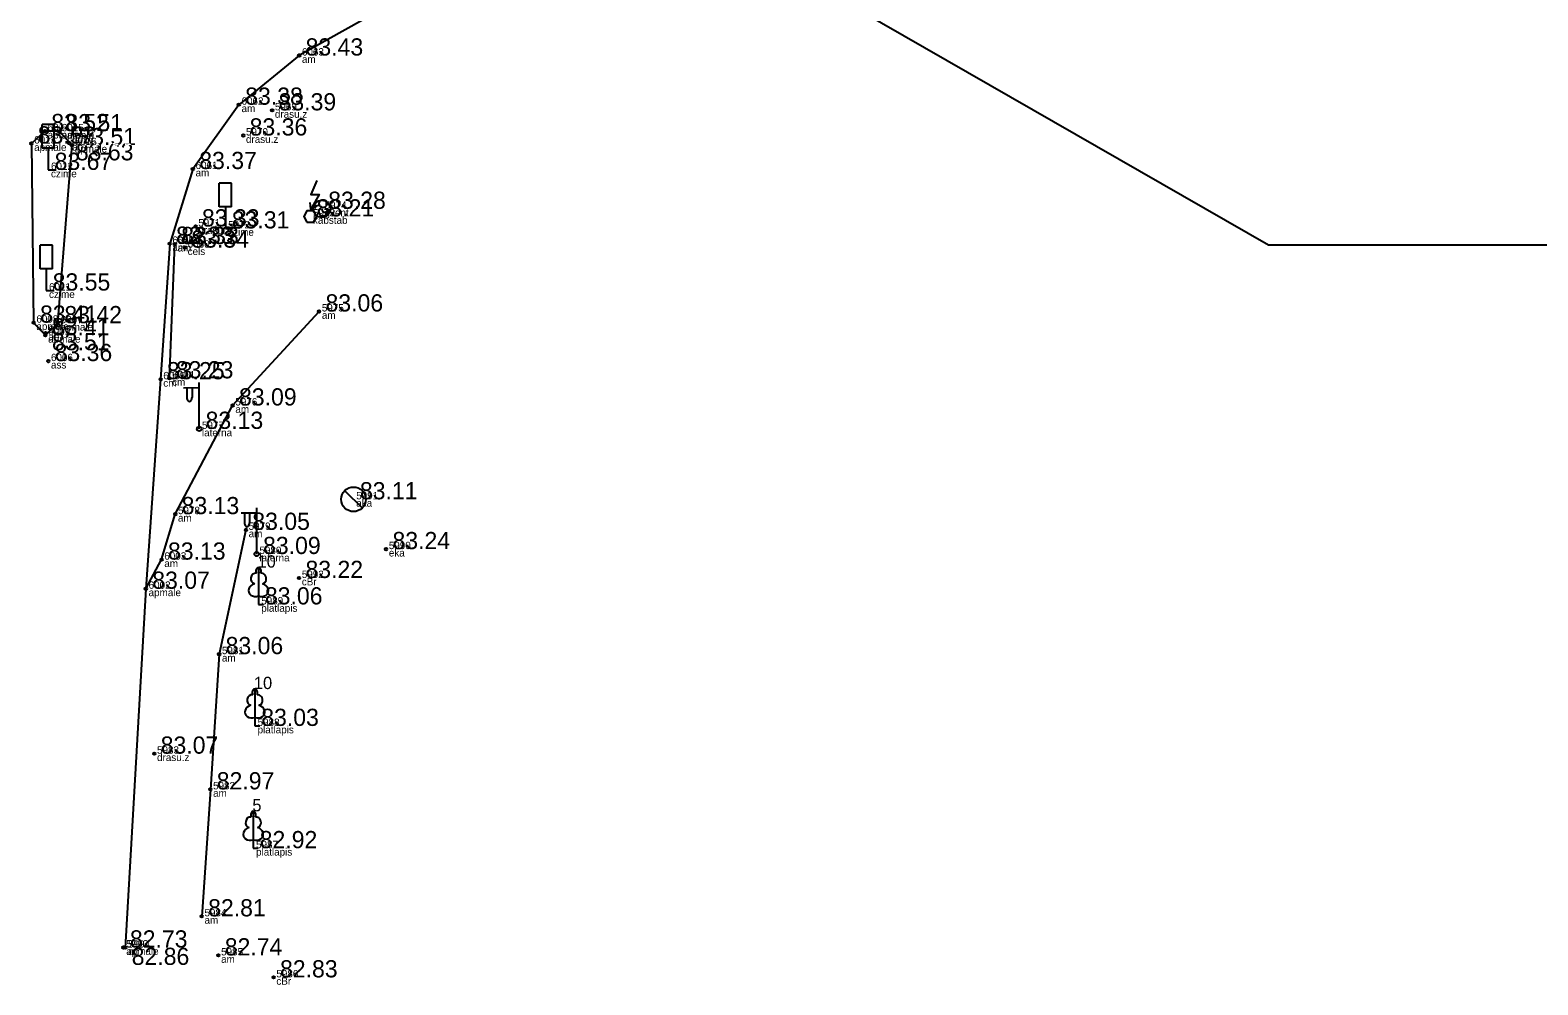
# Model space of a CAD drawing. Extents: x 614911 to 615803, y 262110 to 264311.
# Drawn here: x 615511.4 to 615572.7, y 262591.5 to 262630.3 of the extents above; entities that cross this region are included whole.
import ezdxf

# ---------------------------------------------------------------- set-up
doc = ezdxf.new("R2010")
doc.units = 0
for name, color, linetype in [('Level 1', 7, 'Continuous'), ('Level 12', 7, 'Continuous'), ('Level 16', 7, 'Continuous'), ('Level 27', 7, 'Continuous'), ('Level 37', 7, 'Continuous'), ('Level 44', 7, 'Continuous'), ('Level 53', 7, 'Continuous'), ('Level 54', 7, 'Continuous'), ('Level 57', 7, 'Continuous'), ('Level 58', 7, 'Continuous'), ('Level 63', 7, 'Continuous')]:
    doc.layers.add(name, color=color, linetype=linetype)

msp = doc.modelspace()

# ---------------------------------------------------------------- linework, layer by layer
at = {"layer": 'Level 1'}
for p, q in [((615520.722, 262607.314), (615520.722, 262606.967)), ((615520.722, 262606.967), (615520.922, 262606.967)), ((615520.574, 262602.371), (615520.574, 262602.024)), ((615520.574, 262602.024), (615520.774, 262602.024)), ((615520.511, 262597.397), (615520.511, 262597.05)), ((615520.511, 262597.05), (615520.711, 262597.05))]:
    msp.add_line(p, q, dxfattribs=at)
for points in [[(615520.722, 262608.467), (615520.722, 262607.314)], [(615520.812, 262608.235), (615520.811, 262608.236)], [(615520.574, 262603.524), (615520.574, 262602.371)], [(615520.664, 262603.292), (615520.663, 262603.293)], [(615520.511, 262598.55), (615520.511, 262597.397)], [(615520.601, 262598.318), (615520.6, 262598.319)]]:
    msp.add_lwpolyline(points, dxfattribs=at)
for centre, major_axis, ratio, start_param, end_param in [((615520.594, 262608.022), (-0.039, -0.212), 0.861323, 3.141593, 6.283185), ((615520.722, 262608.317), (0, -0.15), 0.707107, 3.14537, 5.287485), ((615520.722, 262608.317), (0, -0.15), 0.707107, 0.995701, 3.137816), ((615520.85, 262608.022), (0.039, -0.212), 0.861323, 0, 3.141593), ((615520.632, 262607.56), (0.307, 0.095), 0.814445, 1.570796, 4.752015), ((615520.812, 262607.56), (-0.307, 0.095), 0.814445, 1.531171, 4.712389), ((615520.574, 262603.374), (0, -0.15), 0.707107, 3.14537, 5.287485), ((615520.574, 262603.374), (0, -0.15), 0.707107, 0.995701, 3.137816), ((615520.484, 262602.617), (0.307, 0.095), 0.814445, 1.570796, 4.752015), ((615520.446, 262603.079), (-0.039, -0.212), 0.861323, 3.141593, 6.283185), ((615520.664, 262602.617), (-0.307, 0.095), 0.814445, 1.531171, 4.712389), ((615520.702, 262603.079), (0.039, -0.212), 0.861323, 0, 3.141593), ((615520.511, 262598.4), (0, -0.15), 0.707107, 3.14537, 5.287485), ((615520.511, 262598.4), (0, -0.15), 0.707107, 0.995701, 3.137816), ((615520.421, 262597.643), (0.307, 0.095), 0.814445, 1.570796, 4.752015), ((615520.383, 262598.105), (-0.039, -0.212), 0.861323, 3.141593, 6.283185), ((615520.601, 262597.643), (-0.307, 0.095), 0.814445, 1.531171, 4.712389), ((615520.639, 262598.105), (0.039, -0.212), 0.861323, 0, 3.141593)]:
    msp.add_ellipse(centre, major_axis=major_axis, ratio=ratio, start_param=start_param, end_param=end_param, dxfattribs=at)
at = {"layer": 'Level 12'}
for p, q in [((615522.849, 262623.053), (615523.09, 262623.192)), ((615524.226, 262611.592), (615524.944, 262610.896)), ((615524.585, 262611.244), (615524.584, 262611.243))]:
    msp.add_line(p, q, dxfattribs=at)
msp.add_lwpolyline([(615523.098, 262624.215), (615522.849, 262623.652), (615523.185, 262623.652), (615522.849, 262623.053), (615522.827, 262623.323)], dxfattribs=at)
msp.add_lwpolyline([(615522.693, 262622.523), (615522.959, 262622.523), (615523.092, 262622.753), (615522.959, 262622.984), (615522.693, 262622.984), (615522.56, 262622.753)], close=True, dxfattribs=at)
msp.add_circle((615524.585, 262611.244), 0.5, dxfattribs=at)
at = {"layer": 'Level 16'}
for p, q in [((615512.419, 262626.493), (615511.919, 262626.493)), ((615511.919, 262625.524), (615511.919, 262626.493)), ((615512.419, 262625.524), (615512.419, 262626.493)), ((615512.419, 262625.524), (615511.919, 262625.524)), ((615512.173, 262625.524), (615512.173, 262624.646)), ((615512.173, 262624.646), (615512.488, 262624.646)), ((615519.622, 262624.112), (615519.122, 262624.112)), ((615519.122, 262623.143), (615519.122, 262624.112)), ((615519.622, 262623.143), (615519.622, 262624.112)), ((615519.622, 262623.143), (615519.122, 262623.143)), ((615519.376, 262623.143), (615519.376, 262622.265)), ((615519.376, 262622.265), (615519.691, 262622.265)), ((615512.339, 262621.585), (615511.839, 262621.585)), ((615511.839, 262620.616), (615511.839, 262621.585)), ((615512.339, 262620.616), (615512.339, 262621.585)), ((615512.339, 262620.616), (615511.839, 262620.616)), ((615512.093, 262620.616), (615512.093, 262619.738)), ((615512.093, 262619.738), (615512.408, 262619.738))]:
    msp.add_line(p, q, dxfattribs=at)
at = {"layer": 'Level 27'}
msp.add_circle((615523.297, 262623.062), 0.35, dxfattribs=at)
for centre, start, end in [((615523.157, 262623.062), 0, 180), ((615523.437, 262623.062), 180, 0)]:
    msp.add_arc(centre, 0.14, start, end, dxfattribs=at)
at = {"layer": 'Level 37'}
for p, q in [((615517.1, 262616.166), (615517.319, 262621.627)), ((615516.142, 262607.604), (615516.781, 262608.79))]:
    msp.add_line(p, q, dxfattribs=at)
for points in [[(615562.286, 262660.31), (615545.551, 262654.079), (615542.836, 262652.928), (615535.338, 262645.035), (615534.411, 262642.655), (615532.37, 262638.233), (615529.075, 262633.891), (615526.117, 262631.394), (615522.377, 262629.299), (615519.921, 262627.298), (615518.053, 262624.681), (615517.11, 262621.642), (615516.739, 262616.128), (615516.142, 262607.604), (615515.306, 262593.001)], [(615516.781, 262608.79), (615516.781, 262608.79), (615517.337, 262610.64), (615519.67, 262615.062), (615523.187, 262618.886)], [(615520.21, 262610.001), (615519.124, 262604.944), (615518.764, 262599.443), (615518.414, 262594.277)]]:
    msp.add_lwpolyline(points, dxfattribs=at)
msp.add_lwpolyline([(615511.579, 262618.431), (615512.059, 262617.918), (615512.568, 262618.408), (615513.14, 262625.654), (615512.612, 262626.218), (615512.037, 262626.224), (615511.487, 262625.719)], close=True, dxfattribs=at)
at = {"layer": 'Level 44'}
for p, q in [((615518.311, 262615.777), (615517.676, 262615.772)), ((615517.811, 262615.773), (615517.811, 262615.381)), ((615518.021, 262615.775), (615518.021, 262615.381)), ((615518.311, 262614.11), (615518.311, 262615.993)), ((615520.648, 262610.685), (615520.013, 262610.68)), ((615520.148, 262610.681), (615520.148, 262610.289)), ((615520.358, 262610.683), (615520.358, 262610.289)), ((615520.648, 262609.018), (615520.648, 262610.901))]:
    msp.add_line(p, q, dxfattribs=at)
for centre in [(615518.311, 262614.11), (615520.648, 262609.018)]:
    msp.add_circle(centre, 0.09, dxfattribs=at)
for centre in [(615517.916, 262615.381), (615520.253, 262610.289)]:
    msp.add_ellipse(centre, major_axis=(0, 0.151), ratio=0.695971, start_param=1.570796, end_param=4.712389, dxfattribs=at)
at = {"layer": 'Level 57'}
for centre in [(615522.377, 262629.299), (615519.921, 262627.298), (615521.278, 262627.067), (615512.037, 262626.224), (615512.612, 262626.218), (615520.102, 262626.046), (615511.487, 262625.719), (615513.035, 262625.734), (615513.14, 262625.654), (615518.053, 262624.681), (615518.162, 262622.346), (615517.11, 262621.642), (615517.319, 262621.627), (615517.73, 262621.483), (615523.187, 262618.886), (615511.579, 262618.431), (615512.064, 262618.008), (615512.568, 262618.408), (615512.059, 262617.918), (615512.172, 262616.867), (615517.1, 262616.166), (615516.739, 262616.128), (615519.67, 262615.062), (615517.337, 262610.64), (615520.21, 262610.001), (615516.781, 262608.79), (615525.91, 262609.217), (615516.142, 262607.604), (615522.372, 262608.043), (615519.124, 262604.944), (615516.485, 262600.895), (615518.764, 262599.443), (615518.414, 262594.277), (615515.233, 262593.009), (615515.306, 262593.001), (615519.09, 262592.688), (615521.337, 262591.794)]:
    msp.add_circle(centre, 0.05, dxfattribs=at)
at = {"layer": 'Level 58'}
for centre in [(615522.377, 262629.299), (615519.921, 262627.298), (615521.278, 262627.067), (615512.037, 262626.224), (615512.612, 262626.218), (615520.102, 262626.046), (615511.487, 262625.719), (615513.035, 262625.734), (615513.14, 262625.654), (615518.053, 262624.681), (615518.162, 262622.346), (615517.11, 262621.642), (615517.319, 262621.627), (615517.73, 262621.483), (615523.187, 262618.886), (615511.579, 262618.431), (615512.064, 262618.008), (615512.568, 262618.408), (615512.059, 262617.918), (615512.172, 262616.867), (615517.1, 262616.166), (615516.739, 262616.128), (615519.67, 262615.062), (615517.337, 262610.64), (615520.21, 262610.001), (615516.781, 262608.79), (615525.91, 262609.217), (615516.142, 262607.604), (615522.372, 262608.043), (615519.124, 262604.944), (615516.485, 262600.895), (615518.764, 262599.443), (615518.414, 262594.277), (615515.233, 262593.009), (615515.306, 262593.001), (615519.09, 262592.688), (615521.337, 262591.794)]:
    msp.add_circle(centre, 0.05, dxfattribs=at)
at = {"layer": 'Level 63'}
msp.add_lwpolyline([(615512.005, 262650.191), (615561.786, 262621.596), (615647.509, 262621.596)], dxfattribs=at)

# ---------------------------------------------------------------- texts
at = {"layer": 'Level 1'}
for s, p in [(' 10', (615520.497, 262608.467)), (' 10', (615520.349, 262603.524)), (' 5', (615520.286, 262598.55))]:
    msp.add_text(s, height=0.5, dxfattribs=at).set_placement(p)
at = {"layer": 'Level 27'}
msp.add_text(' 83.28', height=0.7, dxfattribs=at).set_placement((615523.297, 262623.062))
at = {"layer": 'Level 53'}
for s, p in [(' am', (615522.377, 262628.999)), (' am', (615519.921, 262626.998)), (' drasu.z', (615521.278, 262626.767)), (' apmale', (615512.037, 262625.924)), (' apmale', (615512.612, 262625.918)), (' drasu.z', (615520.102, 262625.746)), (' apmale', (615511.487, 262625.419)), (' ap', (615513.035, 262625.434)), (' apmale', (615513.14, 262625.354)), (' czime', (615512.173, 262624.346)), (' am', (615518.053, 262624.381)), (' gvent', (615523.297, 262622.762)), (' drasu.z', (615518.162, 262622.046)), (' kabstab', (615522.826, 262622.453)), (' czime', (615519.376, 262621.965)), (' am', (615517.11, 262621.342)), (' am', (615517.319, 262621.327)), (' cels', (615517.73, 262621.183)), (' czime', (615512.093, 262619.438)), (' am', (615523.187, 262618.586)), (' apmale', (615511.579, 262618.131)), (' apmale', (615512.568, 262618.108)), (' apmale', (615512.059, 262617.618)), (' ap', (615512.064, 262617.708)), (' ass', (615512.172, 262616.567)), (' cm', (615516.739, 262615.828)), (' cm', (615517.1, 262615.866)), (' am', (615519.67, 262614.762)), (' laterna', (615518.311, 262613.81)), (' aka', (615524.585, 262610.944)), (' am', (615517.337, 262610.34)), (' am', (615520.21, 262609.701)), (' laterna', (615520.648, 262608.718)), (' eka', (615525.91, 262608.917)), (' am', (615516.781, 262608.49)), (' apmale', (615516.142, 262607.304)), (' cBr', (615522.372, 262607.743)), (' platlapis', (615520.722, 262606.667)), (' am', (615519.124, 262604.644)), (' platlapis', (615520.574, 262601.724)), (' drasu.z', (615516.485, 262600.595)), (' am', (615518.764, 262599.143)), (' platlapis', (615520.511, 262596.75)), (' am', (615518.414, 262593.977)), (' apmale', (615515.233, 262592.709)), (' ap', (615515.306, 262592.701)), (' am', (615519.09, 262592.388)), (' cBr', (615521.337, 262591.494))]:
    msp.add_text(s, height=0.3, dxfattribs=at).set_placement(p)
at = {"layer": 'Level 54'}
for s, p in [(' 6063', (615522.377, 262629.299)), (' 6062', (615519.921, 262627.298)), (' 5969', (615521.278, 262627.067)), (' 6013', (615511.487, 262625.719)), (' 6014', (615512.037, 262626.224)), (' 6015', (615512.612, 262626.218)), (' 6017', (615513.035, 262625.734)), (' 5970', (615520.102, 262626.046)), (' 6016', (615513.14, 262625.654)), (' 6012', (615512.173, 262624.646)), (' 6061', (615518.053, 262624.681)), (' 5973', (615522.826, 262622.753)), (' 5974', (615523.297, 262623.062)), (' 5971', (615518.162, 262622.346)), (' 5972', (615519.376, 262622.265)), (' 6058', (615517.11, 262621.642)), (' 6059', (615517.319, 262621.627)), (' 6060', (615517.73, 262621.483)), (' 6011', (615512.093, 262619.738)), (' 6008', (615511.579, 262618.431)), (' 6007', (615512.568, 262618.408)), (' 5975', (615523.187, 262618.886)), (' 6009', (615512.059, 262617.918)), (' 6010', (615512.064, 262618.008)), (' 6006', (615512.172, 262616.867)), (' 6005', (615516.739, 262616.128)), (' 6004', (615517.1, 262616.166)), (' 5976', (615519.67, 262615.062)), (' 5977', (615518.311, 262614.11)), (' 5991', (615524.585, 262611.244)), (' 5978', (615517.337, 262610.64)), (' 5979', (615520.21, 262610.001)), (' 5990', (615525.91, 262609.217)), (' 6003', (615516.781, 262608.79)), (' 5980', (615520.648, 262609.018)), (' 5992', (615522.372, 262608.043)), (' 6002', (615516.142, 262607.604)), (' 5989', (615520.722, 262606.967)), (' 5981', (615519.124, 262604.944)), (' 5988', (615520.574, 262602.024)), (' 5983', (615516.485, 262600.895)), (' 5982', (615518.764, 262599.443)), (' 5987', (615520.511, 262597.05)), (' 5984', (615518.414, 262594.277)), (' 5993', (615515.233, 262593.009)), (' 5994', (615515.306, 262593.001)), (' 5985', (615519.09, 262592.688)), (' 5986', (615521.337, 262591.794))]:
    msp.add_text(s, height=0.3, dxfattribs=at).set_placement(p)
at = {"layer": 'Level 58'}
for s, p in [(' 83.43', (615522.377, 262629.299)), (' 83.38', (615519.921, 262627.298)), (' 83.39', (615521.278, 262627.067)), (' 83.52', (615512.037, 262626.224)), (' 83.51', (615512.612, 262626.218)), (' 83.36', (615520.102, 262626.046)), (' 83.52', (615511.487, 262625.719)), (' 83.51', (615513.14, 262625.654)), (' 83.63', (615513.035, 262625.034)), (' 83.37', (615518.053, 262624.681)), (' 83.67', (615512.173, 262624.646)), (' 83.33', (615518.162, 262622.346)), (' 83.31', (615519.376, 262622.265)), (' 83.21', (615522.826, 262622.753)), (' 83.33', (615517.11, 262621.642)), (' 83.33', (615517.319, 262621.627)), (' 83.34', (615517.73, 262621.483)), (' 83.55', (615512.093, 262619.738)), (' 83.06', (615523.187, 262618.886)), (' 83.41', (615511.579, 262618.431)), (' 83.42', (615512.568, 262618.408)), (' 83.41', (615512.059, 262617.918)), (' 83.51', (615512.064, 262617.308)), (' 83.36', (615512.172, 262616.867)), (' 83.25', (615516.739, 262616.128)), (' 83.23', (615517.1, 262616.166)), (' 83.09', (615519.67, 262615.062)), (' 83.13', (615518.311, 262614.11)), (' 83.11', (615524.585, 262611.244)), (' 83.13', (615517.337, 262610.64)), (' 83.05', (615520.21, 262610.001)), (' 83.13', (615516.781, 262608.79)), (' 83.09', (615520.648, 262609.018)), (' 83.24', (615525.91, 262609.217)), (' 83.07', (615516.142, 262607.604)), (' 83.22', (615522.372, 262608.043)), (' 83.06', (615520.722, 262606.967)), (' 83.06', (615519.124, 262604.944)), (' 83.03', (615520.574, 262602.024)), (' 83.07', (615516.485, 262600.895)), (' 82.97', (615518.764, 262599.443)), (' 82.92', (615520.511, 262597.05)), (' 82.81', (615518.414, 262594.277)), (' 82.73', (615515.233, 262593.009)), (' 82.86', (615515.306, 262592.301)), (' 82.74', (615519.09, 262592.688)), (' 82.83', (615521.337, 262591.794))]:
    msp.add_text(s, height=0.7, dxfattribs=at).set_placement(p)

doc.saveas('drawing.dxf')
